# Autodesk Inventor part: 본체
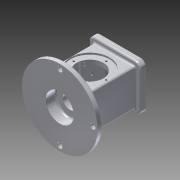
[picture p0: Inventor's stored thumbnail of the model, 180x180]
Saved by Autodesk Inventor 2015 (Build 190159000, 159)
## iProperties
Created: 2019-08
Part Number: 본체
Material: 알루미늄 6061
Document SubType Name: Modeling
Designer: a3
Density: 2.7 g/cm^3
Appearance: 알루미늄 - 평지
Mass: 1040.54 g
Surface Area: 787.873 cm^2
Volume: 385.386 cm^3
Author: a3
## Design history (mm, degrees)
sketch "스케치1"
  geometry: L1 (37, 33)-(-37, 33); L2 (-37, 33)-(-37, -33); L3 (-37, -33)-(37, -33); L4 (37, -33)-(37, 33); 1 further point
  constraints: 8 end point, 2 parallel, 1 horizontal, 1 perpendicular
  dimensions: "d0" = 66 distance of L3.end L1.start; "d1" = 74 distance of L1.start L1.end; "d3" = 37 distance from line of point (0, 0) L4; "d15" = 33 distance from line of point (0, 0) L3
extrude "돌출1" new body sketch "스케치1" stored distance "d4" = 108; taper "d5" = 0 deg
sketch "스케치2"
  geometry: L1 (37, 33)-(-37, 33) reference; L2 (-37, 33)-(-37, -33) reference; L3 (-37, -33)-(37, -33) reference; L4 (37, -33)-(37, 33) reference; C1 r 67.5 at (0, 0); 1 further point
  constraints: 1 centre point, 1 coincident
  dimensions: "d6" = 135 diameter of C1
extrude "돌출2" join sketch "스케치2" distance "d7" = 10; taper "d8" = 0 deg
sketch "스케치3"
  geometry: L1 (-46, 41)-(46, 41); L2 (46, 41)-(46, -41); L3 (46, -41)-(-46, -41); L4 (-46, -41)-(-46, 41); L5 (-37, -33)-(37, -33) reference; L6 (37, -33)-(37, 33) reference; L7 (37, 33)-(-37, 33) reference; L8 (-37, 33)-(-37, -33) reference; 1 further point
  constraints: 8 end point, 2 parallel, 1 horizontal, 1 perpendicular
  dimensions: "d9" = 92 distance of L1.start L1.end; "d10" = 82 distance of L3.end L1.start; "d11" = 46 distance from line of point (0, 0) L4; "d12" = 41 distance from line of point (0, 0) L1
extrude "돌출3" join sketch "스케치3" distance "d13" = 10; taper "d14" = 0 deg
sketch "스케치4"
  geometry: C1 r 25 at (0, 0); 1 further point
  constraints: 1 centre point, 1 coincident
  dimensions: "d16" = 50 diameter of C1
extrude "돌출4" cut sketch "스케치4" distance "d17" = 18; taper "d18" = 0 deg
sketch "스케치5"
  geometry: C1 r 12.5 at (0, 0); 1 further point
  constraints: 1 centre point, 1 coincident
  dimensions: "d19" = 25 diameter of C1
extrude "돌출5" cut sketch "스케치5" stored distance "d20" = 18; taper "d21" = 0 deg
sketch "스케치6"
  geometry: L1 (-46, 41)-(46, 41) reference; L2 (-46, -41)-(-46, 41) reference; L3 (46, -41)-(-46, -41) reference; L4 (46, 41)-(46, -41) reference; L5 (26, 26)-(-26, 26); L6 (-26, 26)-(-26, -26); L7 (-26, -26)-(26, -26); L8 (26, -26)-(26, 26); C1 r 12.5 at (0, 0) reference; 1 further point
  constraints: 8 end point, 2 parallel, 1 horizontal, 1 perpendicular
  dimensions: "d22" = 52 distance of L7.end L5.start; "d23" = 52 distance of L5.start L5.end; "d24" = 26 distance from line of point (0, 0) L8; "d25" = 26 distance from line of point (0, 0) L5
extrude "돌출6" cut sketch "스케치6" distance "d26" = 8; taper "d27" = 0 deg
sketch "스케치7"
  geometry: L1 (-26, 26)-(26, 26) reference; L2 (-26, -26)-(-26, 26) reference; L3 (26, -26)-(-26, -26) reference; L4 (26, 26)-(26, -26) reference; L5 (22, 22)-(-22, 22); L6 (-22, 22)-(-22, -22); L7 (-22, -22)-(22, -22); L8 (22, -22)-(22, 22); C1 r 12.5 at (0, 0) reference; 1 further point
  constraints: 8 end point, 2 parallel, 1 horizontal, 1 perpendicular
  dimensions: "d28" = 44 distance of L7.end L5.start; "d29" = 44 distance of L5.start L5.end; "d30" = 22 distance from line of point (0, 0) L5; "d31" = 22 distance from line of L8 point (0, 0)
extrude "돌출7" cut sketch "스케치7" distance "d32" = 74; taper "d33" = 0 deg
node "작업 평면1"
sketch "스케치9"
  geometry: C1 r 59 at (0, 0); 1 further point
  constraints: 1 centre point, 1 coincident, 1 other
  dimensions: "d36" = 118 diameter of C1
feature "엠보싱1" sketch "스케치9" dims "d0" = 66, "d1" = 74, "d3" = 37, "d15" = 33, "d37" = 0.5, "d38" = 0
sketch "스케치11"
  geometry: C1 r 35 at (37, 44); 1 further point
  constraints: 1 centre point, 1 coincident
  dimensions: "d39" = 70 diameter of C1
extrude "돌출8" cut sketch "스케치11" distance "d40" = 3; taper "d41" = 0 deg
sketch "스케치12"
  geometry: C1 r 24 at (0, 0); 1 further point
  constraints: 1 centre point, 1 coincident
  dimensions: "d42" = 48 diameter of C1
extrude "돌출9" cut sketch "스케치12" stored distance "d43" = 8; taper "d44" = 0 deg
sketch "스케치13"
  geometry: C1 r 35 at (37, 44); 1 further point
  constraints: 1 centre point, 1 coincident
  dimensions: "d45" = 70 diameter of C1
extrude "돌출10" cut sketch "스케치13" distance "d46" = 3; taper "d47" = 0 deg
sketch "스케치14"
  geometry: L1 (100.5, -10)-(-34.5, -10) reference; 3 further points
  constraints: 2 vertical alignment
  dimensions: "d48" = 37 distance from line of L1 point (33, 27); "d49" = 43 distance of point (33, 27) point (33, 70)
hole "구멍1" sketch "스케치14" at (33, 70), (33, 27) diameter "d50" = 4.917; stored, may be unused: countersink angle "d54" = 90 deg, drill point angle "d56" = 118 deg; dims "d51" = 30, "d52" = 4, "d53" = 2, "d55" = 39.6
fillet "모깎기1" dims "d57" = 10
sketch "스케치16"
  geometry: L1 (-26, -26)-(-26, 26) reference; L2 (-26, 26)-(26, 26) reference; L3 (26, 26)-(26, -26) reference; L4 (26, -26)-(-26, -26) reference; L5 (-46, -31)-(-46, 31) reference; L6 (36, -41)-(-36, -41) reference; L7 (46, 31)-(46, -31) reference; L8 (-36, 41)-(36, 41) reference; A1 r 10 centre (-36, 31) between (-36, 41) and (-46, 31) reference; A2 r 10 centre (-36, -31) between (-46, -31) and (-36, -41) reference; A3 r 10 centre (36, -31) between (36, -41) and (46, -31) reference; A4 r 10 centre (36, 31) between (46, 31) and (36, 41) reference; 5 further points
  constraints: 4 coincident
hole "구멍2" sketch "스케치16" at (-36, -31), (-36, 31), (36, 31), (36, -31) diameter "d58" = 3.242; stored, may be unused: countersink angle "d62" = 90 deg, drill point angle "d64" = 118 deg; dims "d59" = 4, "d60" = 4, "d61" = 2, "d63" = 6
sketch "스케치17"
  geometry: A1 r 29 centre (0, 0) between (0, 29) and (-29, 0); 3 further points
  constraints: 4 point on circle, 2 horizontal alignment, 2 vertical alignment, 1 centre point, 1 coincident
  dimensions: "d65" = 58 diameter of A1
hole "구멍3" sketch "스케치17" at (0, 29), (-29, 0), (0, -29), (29, 0) diameter "d66" = 3.242; stored, may be unused: countersink angle "d70" = 90 deg, drill point angle "d72" = 118 deg; dims "d67" = 4, "d68" = 4, "d69" = 2, "d71" = 6
sketch "스케치18"
  geometry: A1 r 59 centre (0, 0) between (59, 0) and (0, 59); 2 further points
  constraints: 3 point on circle, 2 vertical alignment, 1 centre point, 1 coincident, 1 horizontal alignment
  dimensions: "d73" = 118 diameter of A1
hole "구멍4" sketch "스케치18" at (59, 0), (0, 59), (0, -59) diameter "d74" = 9; stored, may be unused: countersink angle "d78" = 90 deg, drill point angle "d80" = 118 deg; dims "d75" = 4, "d76" = 4, "d77" = 2, "d79" = 6
chamfer "모따기1" distance "d81" = 3; stored, may be unused: second distance "d82" = 2, angle "d83" = 45 deg
fillet "모깎기2" dims "d84" = 3
fillet "모깎기3" dims "d85" = 3
fillet "모깎기4" dims "d86" = 3
fillet "모깎기5" dims "d87" = 3
fillet "모깎기6" dims "d88" = 3
fillet "모깎기7" dims "d89" = 3
chamfer "모따기2" distance "d90" = 1; stored, may be unused: second distance "d91" = 2, angle "d92" = 45 deg
fillet "모깎기8" dims "d93" = 3
node "솔리드1"
mirror "대칭1"
node "투영된 루프1"
node "투영된 루프2"
node "투영된 루프3"
node "투영된 루프4"
node "투영된 루프6"
other parameters: "d35" = 88
